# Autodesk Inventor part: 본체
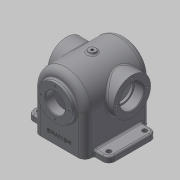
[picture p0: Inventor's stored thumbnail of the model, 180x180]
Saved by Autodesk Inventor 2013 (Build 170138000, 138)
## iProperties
Created: 2019-05
Part Number: 본체
Material: 알루미늄 6061
Document SubType Name: Modeling
Designer: mduedu
Density: 2.71 g/cm^3
Mass: 1068.38 g
Surface Area: 1001.39 cm^2
Volume: 394.235 cm^3
Author: mduedu
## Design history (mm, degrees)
sketch "스케치1"
  geometry: L1 (-55, 0)-(55, 0); L2 (55, 0)-(55, 110); L3 (55, 110)-(-55, 110); L4 (-55, 110)-(-55, 0); 2 further points
  constraints: 8 end point, 2 parallel, 1 coincident, 1 horizontal, 1 midpoint, 1 perpendicular
  dimensions: "d0" = 110 distance of L3.end L1.start; "d2" = 110 distance of L2.end L3.end
extrude "돌출1" new body sketch "스케치1" stored distance "d3" = 86; taper "d4" = 0 deg
fillet "모깎기1"
fillet "모깎기2" dims "d5" = 11
feature "쉘1" dims "d6" = 8
sketch "스케치2"
  geometry: C1 r 29 at (-32, 67); A1 r 43 centre (-32, 67) between (11, 67) and (-75, 67) reference; 1 further point
  constraints: 1 centre point, 1 coincident
  dimensions: "d7" = 58 diameter of C1
extrude "돌출2" join sketch "스케치2" distance "d8" = 7; taper "d9" = 0 deg
fillet "모깎기3" dims "d10" = 3
hole "구멍1" diameter "d13" = 33; stored, may be unused: countersink angle "d17" = 90 deg, drill point angle "d19" = 118 deg; dims "d11" = 10, "d12" = 10, "d14" = 6, "d15" = 4, "d16" = 2, "d18" = 8
node "작업 평면1"
sketch "스케치3"
  geometry: L1 (18, -29)-(18, 29) reference; L2 (-99, 0)-(-99, 32) reference; C1 r 31 at (-56, 0); 2 further points
  constraints: 1 centre point, 1 horizontal alignment, 1 midpoint
  dimensions: "d21" = 62 diameter of C1; "d24" = 43 distance from line of C1.centre L2
extrude "돌출3" join sketch "스케치3" stored distance "d25" = 5; taper "d26" = 0 deg
hole "구멍2" diameter "d29" = 40; stored, may be unused: countersink angle "d33" = 90 deg, drill point angle "d35" = 0 deg; dims "d27" = 10, "d28" = 10, "d30" = 6, "d31" = 4, "d32" = 2, "d34" = 16
hole "구멍3" diameter "d38" = 35; stored, may be unused: countersink angle "d42" = 90 deg, drill point angle "d44" = 0 deg; dims "d36" = 10, "d37" = 10, "d39" = 6, "d40" = 4, "d41" = 2, "d43" = 16
fillet "모깎기4" dims "d45" = 3
chamfer "모따기1" distance "d46" = 1; stored, may be unused: second distance "d47" = 2, angle "d48" = 45 deg
chamfer "모따기2" distance "d49" = 1; stored, may be unused: second distance "d50" = 2, angle "d51" = 45 deg
fillet "모깎기5" dims "d52" = 0.3
node "작업 평면2"
sketch "스케치4"
  geometry: L1 (11, 75)-(11, 11) reference; C1 r 6 at (-44, 43); 1 further point
  constraints: 1 centre point, 1 coincident
  dimensions: "d54" = 12 diameter of C1; "d67" = 55 distance from line of point (-44, 43) L1 (derived)
extrude "돌출4" join sketch "스케치4" stored distance "d55" = 5; taper "d56" = 0 deg
hole "구멍4" diameter "d59" = 4.134; stored, may be unused: countersink angle "d63" = 90 deg, drill point angle "d65" = 0 deg; dims "d57" = 10, "d58" = 10, "d60" = 6, "d61" = 4, "d62" = 2, "d64" = 16
fillet "모깎기6" dims "d66" = 3
sketch "스케치5"
  geometry: L1 (47, -32)-(47, 32) reference; L2 (44, 35)-(-44, 35) reference; L3 (-47, 32)-(-47, -32) reference; L4 (-44, -35)-(44, -35) reference; L5 (-44, -43)-(44, -43) reference; L6 (-55, -32)-(-55, 32) reference; L7 (44, 43)-(-44, 43) reference; L8 (55, 32)-(55, -32) reference; L9 (40, 43)-(-40, 43); L10 (-40, 43)-(-40, 68); L11 (-40, 68)-(40, 68); L12 (40, 68)-(40, 43); A1 r 3 centre (44, -32) between (44, -35) and (47, -32) reference; A2 r 3 centre (44, 32) between (47, 32) and (44, 35) reference; A3 r 3 centre (-44, 32) between (-44, 35) and (-47, 32) reference; A4 r 3 centre (-44, -32) between (-47, -32) and (-44, -35) reference; A5 r 11 centre (44, -32) between (44, -43) and (55, -32) reference; A6 r 11 centre (-44, -32) between (-55, -32) and (-44, -43) reference; A7 r 11 centre (-44, 32) between (-44, 43) and (-55, 32) reference; A8 r 11 centre (44, 32) between (55, 32) and (44, 43) reference; 1 further point
  constraints: 8 end point, 2 parallel, 1 horizontal, 1 perpendicular, 1 point on line
  dimensions: "d68" = 15 distance between parallel lines of L12 L8; "d71" = 80 distance of L10.end L11.end; "d72" = 25 distance between parallel lines of L11 L7
extrude "돌출5" join sketch "스케치5" distance "d73" = 10; taper "d74" = 0 deg
fillet "모깎기7" dims "d76" = 10
sketch "스케치6"
  geometry: L1 (-40, -43)-(-40, -58) reference; L2 (-30, -68)-(30, -68) reference; L3 (40, -58)-(40, -43) reference; L4 (-40, -43)-(40, -43) reference; C1 r 4 at (-30, -58); C2 r 4 at (30, -58); A1 r 10 centre (30, -58) between (30, -68) and (40, -58) reference; A2 r 10 centre (-30, -58) between (-40, -58) and (-30, -68) reference; 1 further point
  constraints: 2 centre point, 2 coincident, 1 equal radius
  dimensions: "d77" = 8 diameter of C1
extrude "돌출6" cut sketch "스케치6" stored distance "d78" = 10; taper "d79" = 0 deg
fillet "모깎기8" dims "d80" = 3
fillet "모깎기9" dims "d81" = 3
fillet "모깎기10" dims "d82" = 3
fillet "모깎기11" dims "d83" = 3
sketch "스케치7"
  geometry: L1 (64, 0)-(0, 0) reference; 4 further points
  constraints: 2 midpoint, 2 vertical alignment, 1 other
  dimensions: "d85" = 15 distance of point (32, 15) point (32, 0)
feature "엠보싱1" sketch "스케치7" dims "d7" = 58, "d86" = 0.5, "d87" = 0
sketch "스케치8"
  geometry: 4 further points
  constraints: 4 other
hole "구멍5" sketch "스케치8" at (0, 24), (-24, 0), (0, -24), (24, 0) diameter "d88" = 3.242; stored, may be unused: countersink angle "d92" = 90 deg, drill point angle "d94" = 120 deg; dims "d89" = 8, "d90" = 4, "d91" = 2, "d93" = 10
sketch "스케치9"
  geometry: 4 further points
  constraints: 4 other
hole "구멍7" sketch "스케치9" at (-26, 0), (0, -26), (26, 0), (0, 26) diameter "d95" = 3.242; stored, may be unused: countersink angle "d99" = 90 deg, drill point angle "d101" = 120 deg; dims "d96" = 8, "d97" = 4, "d98" = 2, "d100" = 10
sketch "스케치10"
  geometry: 4 further points
  constraints: 4 other
hole "구멍9" sketch "스케치10" at (0, -26), (26, 0), (-26, 0), (0, 26) diameter "d102" = 3.242; stored, may be unused: countersink angle "d106" = 90 deg, drill point angle "d108" = 120 deg; dims "d103" = 8, "d104" = 4, "d105" = 2, "d107" = 10
node "솔리드1"
mirror "대칭1"
mirror "대칭2"
node "투영된 루프1"
node "투영된 루프2"
other parameters: "d53" = -113
